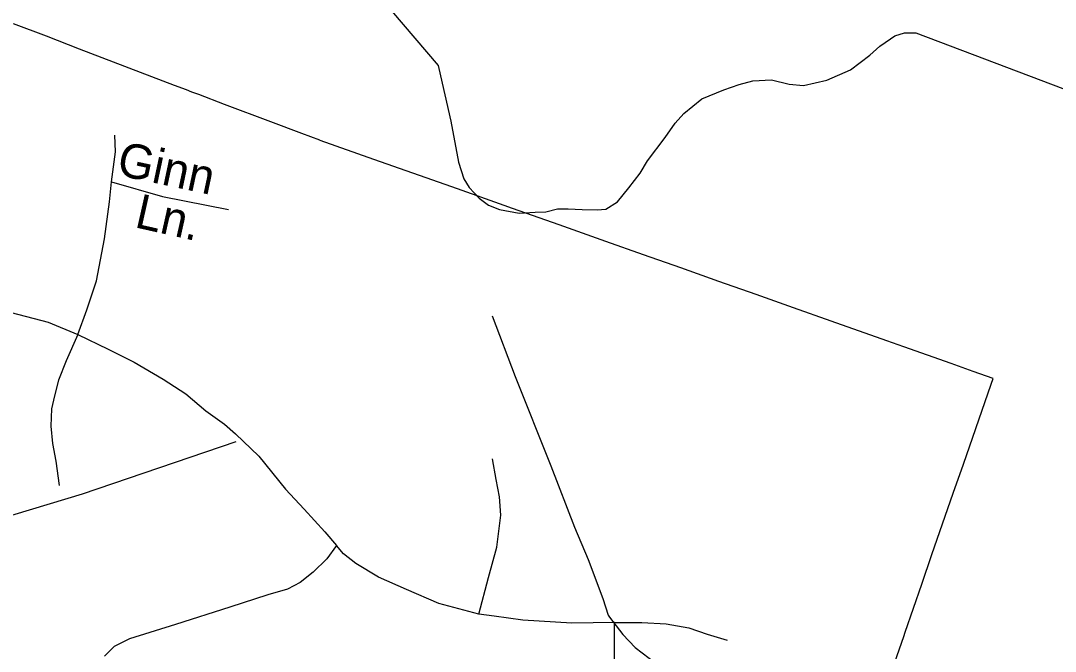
# Model space of a CAD drawing. Extents: x 2315291 to 2336543, y 597177 to 615230.
# Drawn here: x 2327561 to 2330419, y 598769 to 600511 of the extents above; entities that cross this region are included whole.
import ezdxf

# ---------------------------------------------------------------- set-up
doc = ezdxf.new("R2010")
doc.units = 0
for name, color, linetype in [('Exist Boundary Political City Limit New', 7, 'Continuous'), ('Exist Hydrographic Misc Water Feature', 7, 'Continuous'), ('Exist Road Non-System Type 51', 7, 'Continuous'), ('Exist Road Non-System Type 51 Label', 7, 'Continuous'), ('Map Preparation Boundary City Limit Buffer Line', 7, 'Continuous')]:
    doc.layers.add(name, color=color, linetype=linetype)

msp = doc.modelspace()

# ---------------------------------------------------------------- linework, layer by layer
at = {"layer": 'Exist Boundary Political City Limit New'}
for points in [[(2328386.8, 600180.4), (2328337.5, 600198.9), (2328252.2, 600231), (2328124.2, 600279.2), (2328052.8, 600306.2), (2328033.5, 600313.5), (2328018.5, 600319.2), (2327986, 600331.4), (2327723.5, 600432.2), (2327632, 600467.4), (2327541.5, 600502.1)], [(2329957.5, 598686), (2330000, 598809.3), (2330004, 598821.1), (2330049.8, 598954), (2330078, 599036.2), (2330085.2, 599057.1), (2330137, 599205.7), (2330164.8, 599285.6), (2330199, 599384.4), (2330241.5, 599506.5), (2330247, 599522.3), (2330192.2, 599541.7), (2330131.2, 599563.2), (2330000, 599609.7), (2329953.5, 599626.1), (2329800, 599680.4), (2329695.2, 599717.4), (2329592.5, 599753.8), (2329489.8, 599790.1), (2329384.2, 599827.5), (2329281.2, 599863.9), (2329177.5, 599900.6), (2329048.5, 599946.2), (2328919, 599992), (2328896.5, 600000), (2328844.5, 600018.4), (2328821.5, 600026.5), (2328751.8, 600051.2), (2328536, 600127.5), (2328388.2, 600179.8), (2328387.5, 600180.1), (2328386.8, 600180.4)]]:
    msp.add_lwpolyline(points, dxfattribs=at)
at = {"layer": 'Exist Hydrographic Misc Water Feature'}
for points in [[(2327645.9, 600992.9), (2327870.6, 600905.5), (2328058.6, 600843.6), (2328211.4, 600977.1), (2328450.7, 600695.8), (2328713.8, 600386.9), (2328715.8, 600378.9)], [(2328715.8, 600378.9), (2328749.4, 600233.1), (2328770.4, 600119.7), (2328784.9, 600073.7), (2328799.3, 600050), (2328827.4, 600020.2), (2328853.4, 600000.5), (2328883.8, 599989.1), (2328937.9, 599979.3), (2328981.8, 599982), (2329011.9, 599982.3), (2329043.9, 599990.5), (2329073.6, 599990.9), (2329111.8, 599989.2), (2329153.6, 599987.8), (2329177.6, 599989.8), (2329209.6, 600010.2), (2329241, 600048.8), (2329272.3, 600089.1), (2329292, 600123.1), (2329341.4, 600187.8), (2329368.9, 600227.9), (2329392.5, 600254.3), (2329442.1, 600294.7), (2329503.6, 600319.6), (2329545.7, 600334), (2329583.4, 600344.1), (2329635.3, 600346.8), (2329683.5, 600335.1), (2329723.6, 600331.9), (2329787.4, 600346.2), (2329853.4, 600375.2), (2329906.8, 600415.4), (2329934.2, 600440.1), (2329964, 600460.4), (2329975.9, 600468.3), (2330001.9, 600476.6), (2330033.9, 600477), (2330473.5, 600309.9)], [(2328863, 599694.9), (2328926.4, 599527.6), (2329025.2, 599280.8), (2329091.1, 599111.5), (2329128, 599022), (2329169.2, 598914.4), (2329183.7, 598868.9), (2329187.6, 598862.6)], [(2328154.8, 599347.3), (2327730.9, 599203), (2327300.3, 599072.4), (2327156.4, 599090.8), (2326981.5, 598791), (2326826.7, 598529.7)], [(2329187.6, 598862.6), (2329224.1, 598815.3), (2329258.4, 598779.4), (2329296.9, 598750), (2329349.4, 598710.5), (2329381.4, 598680.9), (2329406, 598647.3), (2329440.3, 598615.7), (2329466.9, 598574), (2329487.2, 598530), (2329495.4, 598490.2), (2329499.9, 598440.5), (2329504.7, 598396.4), (2329509.2, 598362.4), (2329511.2, 598342.2), (2329515.5, 598316.5), (2329519.4, 598294.4), (2329526, 598276.8), (2329536.2, 598254.6)]]:
    msp.add_lwpolyline(points, dxfattribs=at)
at = {"layer": 'Exist Road Non-System Type 51'}
for points in [[(2327811.8, 600065.6), (2327823.2, 600148.3), (2327821.3, 600194)], [(2327718.7, 599643.5), (2327743.4, 599711.9), (2327770, 599791.8), (2327792.8, 599907.8), (2327806.1, 600010.5), (2327811.8, 600065.6)], [(2327811.8, 600065.6), (2327952.4, 600024.7), (2328134.9, 599988.6)], [(2327312, 599759.5), (2327412.7, 599736.6), (2327534.4, 599704.3), (2327637, 599677.7), (2327718.7, 599643.5)], [(2327718.7, 599643.5), (2327686.4, 599571.2), (2327665.5, 599518), (2327654.1, 599474.2), (2327646.5, 599438.1), (2327644.6, 599390.6), (2327648.4, 599343), (2327657.9, 599293.6), (2327667.4, 599227)], [(2327718.7, 599643.5), (2327802.3, 599603.5), (2327874.5, 599567.4), (2327954.3, 599519.9), (2328017, 599479.9), (2328072.2, 599432.4), (2328123.5, 599396.3), (2328153.9, 599369.7), (2328218.5, 599307.9), (2328292.6, 599216.6), (2328343.9, 599161.4), (2328400.9, 599098.7), (2328433.2, 599060.6)], [(2328826.6, 598871.4), (2328853.2, 598972.2), (2328876, 599055.9), (2328887.4, 599144.3), (2328883.6, 599195.7), (2328874.1, 599243.2), (2328864.6, 599300.2)], [(2328433.2, 599060.6), (2328406.6, 599023.6), (2328368.6, 598987.4), (2328332.5, 598958.9), (2328298.3, 598939.9), (2328243.2, 598924.7), (2328138.7, 598890.5), (2327988.5, 598842.9), (2327861.2, 598803), (2327819.4, 598782.1), (2327792.8, 598755.5)], [(2328826.6, 598871.4), (2328716.4, 598900.9), (2328627.1, 598939), (2328549.1, 598973.2), (2328486.4, 599011.2), (2328452.2, 599037.8), (2328433.2, 599060.6)], [(2329201, 598848.6), (2329083.1, 598846.7), (2328948.2, 598854.3), (2328868.4, 598865.7), (2328826.6, 598871.4)], [(2329201, 598848.6), (2329277, 598848.6), (2329343.5, 598844.8), (2329406.2, 598833.4), (2329457.5, 598816.3), (2329512.6, 598799.2)], [(2329201, 598742.1), (2329201, 598848.6)]]:
    msp.add_lwpolyline(points, dxfattribs=at)
at = {"layer": 'Map Preparation Boundary City Limit Buffer Line'}
for points in [[(2328386.8, 600180.4), (2328337.5, 600198.9), (2328252.2, 600231), (2328124.2, 600279.2), (2328052.8, 600306.2), (2328033.5, 600313.5), (2328018.5, 600319.2), (2327986, 600331.4), (2327723.5, 600432.2), (2327632, 600467.4), (2327541.5, 600502.1)], [(2329957.5, 598686), (2330000, 598809.3), (2330004, 598821.1), (2330049.8, 598954), (2330078, 599036.2), (2330085.2, 599057.1), (2330137, 599205.7), (2330164.8, 599285.6), (2330199, 599384.4), (2330241.5, 599506.5), (2330247, 599522.3), (2330192.2, 599541.7), (2330131.2, 599563.2), (2330000, 599609.7), (2329953.5, 599626.1), (2329800, 599680.4), (2329695.2, 599717.4), (2329592.5, 599753.8), (2329489.8, 599790.1), (2329384.2, 599827.5), (2329281.2, 599863.9), (2329177.5, 599900.6), (2329048.5, 599946.2), (2328919, 599992), (2328896.5, 600000), (2328844.5, 600018.4), (2328821.5, 600026.5), (2328751.8, 600051.2), (2328536, 600127.5), (2328388.2, 600179.8), (2328387.5, 600180.1), (2328386.8, 600180.4)]]:
    msp.add_lwpolyline(points, dxfattribs=at)

# ---------------------------------------------------------------- texts
at = {"layer": 'Exist Road Non-System Type 51 Label'}
for s, rotation, p in [('Ginn', 347.9833, (2327822.8, 600085.2)), ('Ln.', 347.2818, (2327872.7, 599940.6))]:
    msp.add_text(s, height=95, rotation=rotation, dxfattribs=at).set_placement(p)

doc.saveas('drawing.dxf')
